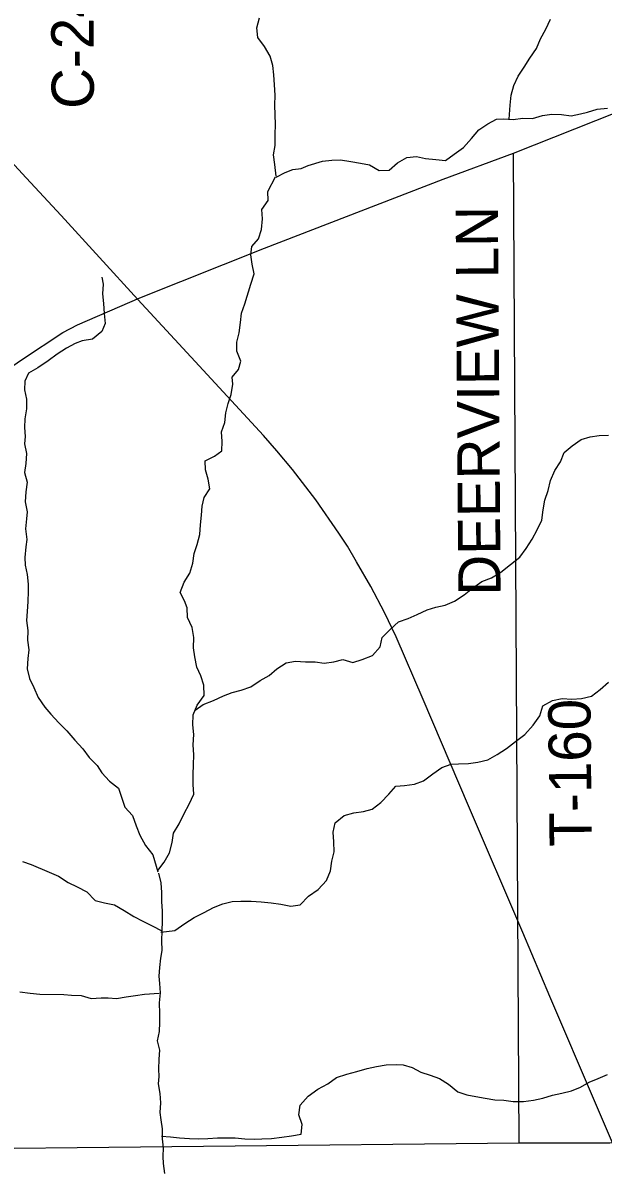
# Model space of a CAD drawing. Extents: x 1985906 to 2277390, y 930619 to 1324581.
# Drawn here: x 2127337 to 2131455, y 1129372 to 1137477 of the extents above; entities that cross this region are included whole.
import ezdxf

# ---------------------------------------------------------------- set-up
doc = ezdxf.new("R2010")
doc.units = 0
for name, color, linetype in [('GM_X_County_Road_Text', 7, 'Continuous'), ('GM_X_Minor_River', 7, 'Continuous'), ('GM_X_Rail_Line', 7, 'Continuous'), ('GM_X_State_Route', 7, 'Continuous'), ('GM_X_Township_Road', 7, 'Continuous'), ('GM_X_Township_Road_Text', 7, 'Continuous'), ('GM_X_US_Route', 7, 'Continuous')]:
    doc.layers.add(name, color=color, linetype=linetype)

msp = doc.modelspace()

# ---------------------------------------------------------------- linework, layer by layer
at = {"layer": 'GM_X_Minor_River'}
for points in [[(2129135.2, 1136388.4), (2129126.3, 1136471.2), (2129115.4, 1136539.6), (2129128.6, 1136607.6), (2129128, 1136685.8), (2129129.2, 1136756), (2129128.4, 1136824.2), (2129125.5, 1136892.5), (2129126.8, 1136964.7), (2129122, 1137037), (2129119.2, 1137107.3), (2129112.4, 1137175.6), (2129093.4, 1137240.2), (2129052.4, 1137309.1), (2129005.3, 1137374.2), (2128998.5, 1137442.5), (2129017.8, 1137512.4)], [(2130789.5, 1136794.9), (2130795, 1136892.5), (2130802.2, 1136964.6), (2130821.5, 1137032.4), (2130852.8, 1137098.1), (2130894.1, 1137163.5), (2130935.4, 1137227), (2130982.8, 1137294.3), (2131010.1, 1137364.1), (2131049.4, 1137431.6), (2131080.8, 1137503.2)], [(2129134.8, 1136382.7), (2129199.6, 1136415.7), (2129252.2, 1136436.8), (2129312.6, 1136443.7), (2129363.2, 1136464.9), (2129464.2, 1136495.2), (2129530.6, 1136504), (2129590.9, 1136504.9), (2129665, 1136493.5), (2129733.1, 1136482.3), (2129797.2, 1136469.1), (2129864.8, 1136429.8), (2129937.2, 1136432.4), (2129996.3, 1136483.5), (2130061.3, 1136522.5), (2130129.7, 1136529.3), (2130195.8, 1136514.1), (2130268, 1136506.7), (2130336.1, 1136499.5), (2130399.2, 1136544.5), (2130464.3, 1136593.5), (2130521.7, 1136656.6), (2130573, 1136717.9), (2130638, 1136760.9), (2130698.8, 1136793.9), (2130749.1, 1136795), (2130817.3, 1136791.7), (2130885.8, 1136800.5), (2130954.1, 1136799.3), (2131024.7, 1136820.1), (2131091.2, 1136828.9), (2131159.5, 1136827.7), (2131227.6, 1136816.4), (2131294.1, 1136831.3), (2131344.6, 1136842.4), (2131413.3, 1136865.2), (2131485.7, 1136872)], [(2128295.7, 1131463), (2128341.2, 1131521.8), (2128378.5, 1131587.3), (2128397.9, 1131661.2), (2128407.1, 1131727.2), (2128446.4, 1131794.7), (2128481.8, 1131866.3), (2128517.1, 1131933.9), (2128550.5, 1132003.5), (2128545.6, 1132071.8), (2128544.9, 1132144), (2128548.1, 1132212.2), (2128551.3, 1132284.3), (2128546.5, 1132354.7), (2128549.8, 1132426.8), (2128542.9, 1132495.2), (2128546.2, 1132567.3), (2128573.5, 1132635.1), (2128624.9, 1132704.3), (2128622.1, 1132776.6), (2128601.2, 1132843.2), (2128572.2, 1132905.9), (2128557.3, 1132978.4), (2128548.4, 1133042.8), (2128551.7, 1133115), (2128538.9, 1133187.4), (2128506, 1133258.2), (2128503.1, 1133326.5), (2128483.9, 1133377), (2128452.8, 1133435.8), (2128482.2, 1133507.4), (2128523.5, 1133572.9), (2128544.8, 1133642.7), (2128552, 1133712.8), (2128575.2, 1133776.6), (2128592.5, 1133846.5), (2128597.7, 1133914.6), (2128604.9, 1133982.7), (2128610, 1134046.8), (2128625.2, 1134108.8), (2128664.4, 1134170.2), (2128651.5, 1134238.7), (2128634.6, 1134305.2), (2128631.7, 1134369.5), (2128696.6, 1134402.4), (2128749.5, 1134439.6), (2128752.6, 1134507.7), (2128747.8, 1134574), (2128771, 1134641.8), (2128778.3, 1134709.9), (2128793.5, 1134775.8), (2128816.7, 1134839.6), (2128828, 1134913.6), (2128822.8, 1134963.9), (2128868, 1135017.2), (2128883.1, 1135077.2), (2128856.2, 1135147.9), (2128855.3, 1135212.1), (2128872.5, 1135278), (2128881.8, 1135350), (2128889, 1135418.1), (2128912.2, 1135483.9), (2128954.8, 1135623.6), (2128978.2, 1135697.4), (2128965.3, 1135765.8), (2128956.4, 1135830.2), (2128963.5, 1135890.3), (2129010.6, 1135945.6), (2129031.9, 1136011.4), (2129037.2, 1136085.6), (2129034.4, 1136153.8), (2129077.6, 1136217.2), (2129074.7, 1136279.5), (2129130.8, 1136384)], [(2127899, 1135672.8), (2127908.1, 1135622.4), (2127902.9, 1135554.3), (2127909.8, 1135486), (2127914.6, 1135415.7), (2127921.4, 1135343.3), (2127898.3, 1135287.6), (2127831.1, 1135232.6), (2127758.6, 1135221.9), (2127708, 1135202.7), (2127647.2, 1135169.7), (2127582.1, 1135126.8), (2127517, 1135079.8), (2127443.8, 1135028.9), (2127376.9, 1134992), (2127351.8, 1134934.3), (2127348.7, 1134872.2), (2127363.6, 1134807.7), (2127364.4, 1134737.4), (2127351.2, 1134667.5), (2127348.1, 1134605.3), (2127353, 1134541), (2127348.1, 1134491), (2127362.9, 1134420.5), (2127357.7, 1134350.3), (2127348.6, 1134286.3), (2127367.5, 1134217.8), (2127358.2, 1134149.7), (2127355, 1134079.5), (2127367.8, 1134007.1), (2127362.9, 1133957), (2127355.7, 1133886.9), (2127366.4, 1133810.5), (2127357.5, 1133758.5), (2127352.2, 1133684.4), (2127353.2, 1133628.2), (2127368.1, 1133561.7), (2127375, 1133493.3), (2127376.1, 1133443.2), (2127372.8, 1133371), (2127367.6, 1133300.9), (2127362.5, 1133236.8), (2127373.3, 1133166.3), (2127370.1, 1133096.2), (2127378.9, 1133027.8), (2127373.9, 1132965.7), (2127368.6, 1132893.6), (2127383.5, 1132825.1), (2127414.5, 1132760.3), (2127445.4, 1132689.6), (2127492.5, 1132622.5), (2127535.8, 1132571.6), (2127593, 1132510.3), (2127650.2, 1132453.1), (2127705.3, 1132387.9), (2127762.5, 1132326.7), (2127807.7, 1132263.7), (2127864.9, 1132206.5), (2127898.2, 1132155.7), (2127951.4, 1132096.6), (2128016.8, 1132047.2), (2128039.7, 1131974.6), (2128060.7, 1131912), (2128115.9, 1131852.8), (2128140.8, 1131780.2), (2128167.7, 1131713.5), (2128206.7, 1131640.6), (2128259.7, 1131573.4), (2128295.7, 1131454.1)], [(2128560.8, 1132599.2), (2128617.8, 1132640.3), (2128690.6, 1132669.1), (2128761.5, 1132701.9), (2128822.1, 1132724.9), (2128886.7, 1132741.8), (2128955.4, 1132764.6), (2129020.5, 1132809.6), (2129085.4, 1132846.5), (2129140.5, 1132893.7), (2129205.5, 1132936.6), (2129272, 1132947.5), (2129344.3, 1132944.1), (2129412.5, 1132942.9), (2129476.7, 1132933.7), (2129543.1, 1132942.6), (2129607.7, 1132959.4), (2129679.6, 1132938.1), (2129746.3, 1132959), (2129819.1, 1132987.7), (2129872.4, 1133049), (2129887.6, 1133114.9), (2129942.9, 1133172.1), (2130004.1, 1133227.2), (2130070.8, 1133250), (2130135.6, 1133278.9), (2130206.4, 1133311.8), (2130269.1, 1133330.7), (2130333.6, 1133345.6), (2130400.4, 1133374.5), (2130469.4, 1133417.4), (2130528.6, 1133466.5), (2130593.7, 1133513.4), (2130662.4, 1133540.3), (2130729.4, 1133579.2), (2130796.7, 1133634.2), (2130863.8, 1133685.1), (2130909.1, 1133746.5), (2130952.5, 1133813.9), (2130987.7, 1133879.5), (2131021.1, 1133949.1), (2131030.4, 1134021.2), (2131041.6, 1134089.2), (2131064.9, 1134159), (2131082.2, 1134228.9), (2131113.6, 1134300.6), (2131152.8, 1134362.1), (2131178.1, 1134427.8), (2131235.2, 1134476.9), (2131300.2, 1134521.9), (2131362.8, 1134540.8), (2131427.3, 1134549.7), (2131493.6, 1134552.5)], [(2128317.7, 1131025.1), (2128415.2, 1131036.9), (2128486.3, 1131085.8), (2128553.4, 1131128.7), (2128624.3, 1131163.5), (2128689.2, 1131200.5), (2128755.9, 1131225.3), (2128822.5, 1131242.2), (2128884.8, 1131245.1), (2128957.1, 1131243.8), (2129027.4, 1131240.5), (2129099.6, 1131233.2), (2129167.7, 1131223.9), (2129239.8, 1131210.6), (2129306.3, 1131219.4), (2129365.6, 1131280.5), (2129432.7, 1131327.5), (2129492.1, 1131392.6), (2129519.4, 1131460.3), (2129530.6, 1131528.3), (2129545.8, 1131594.3), (2129545.1, 1131666.5), (2129540.2, 1131734.8), (2129553.4, 1131800.8), (2129616.6, 1131851.8), (2129685.2, 1131870.6), (2129753.7, 1131881.4), (2129816.3, 1131898.4), (2129877.4, 1131945.4), (2129934.6, 1132004.6), (2129983.8, 1132059.8), (2130046.2, 1132066.8), (2130116.7, 1132075.5), (2130181.4, 1132098.4), (2130246.5, 1132147.4), (2130309.6, 1132194.4), (2130376.3, 1132217.3), (2130428.6, 1132220.3), (2130500.9, 1132221), (2130565.4, 1132231.9), (2130638, 1132248.7), (2130702.9, 1132285.6), (2130770, 1132328.5), (2130833.1, 1132377.6), (2130900.3, 1132428.5), (2130957.7, 1132493.7), (2131007, 1132561), (2131028.3, 1132630.8), (2131095.3, 1132669.8), (2131163.8, 1132682.6), (2131232.1, 1132677.3), (2131302.4, 1132682.1), (2131373, 1132698.8), (2131434.2, 1132747.9), (2131493.3, 1132799)], [(2127334.8, 1131525.9), (2127396.7, 1131504.7), (2127524.3, 1131450.2), (2127590.2, 1131423), (2127659.7, 1131377.6), (2127723.4, 1131346.3), (2127791.1, 1131311), (2127850.3, 1131249.7), (2127916.3, 1131232.5), (2127988.4, 1131219.2), (2128056, 1131179.8), (2128125.6, 1131136.4), (2128189.3, 1131103.2), (2128255, 1131069.9), (2128322.7, 1131034.6)], [(2128299.7, 1131444.2), (2128316.6, 1131375.7), (2128321.4, 1131307.4), (2128322.3, 1131243.2), (2128325.1, 1131174.9), (2128325.9, 1131102.7), (2128324.7, 1131034.5), (2128321.5, 1130962.3), (2128324.3, 1130894.1), (2128315.3, 1130840.1), (2128306.1, 1130774), (2128303, 1130711.9), (2128308.2, 1130661.6), (2128311, 1130593.4), (2128303.8, 1130523.3), (2128306.5, 1130449), (2128307.4, 1130382.8), (2128304.3, 1130320.7), (2128291.1, 1130254.7), (2128306, 1130188.2), (2128302.9, 1130124.1), (2128299.6, 1130051.9), (2128302.7, 1129999.7), (2128297.8, 1129947.6), (2128308.7, 1129881.2), (2128313.5, 1129812.9), (2128310.4, 1129744.8), (2128317.5, 1129692.4), (2128326.5, 1129630.1), (2128327.2, 1129557.9), (2128332.1, 1129493.6), (2128331.1, 1129433.4), (2128334.2, 1129383.2), (2128343, 1129312.8)], [(2127316.7, 1130601.3), (2127388.9, 1130592), (2127459.1, 1130584.7), (2127627.8, 1130581.7), (2127682, 1130578.7), (2127750.2, 1130575.4), (2127822.2, 1130554.1), (2127892.6, 1130558.8), (2127942.8, 1130557.9), (2128001, 1130554.8), (2128071.5, 1130565.6), (2128135.9, 1130574.5), (2128200.4, 1130585.3), (2128304.3, 1130591.6)], [(2128321.5, 1129578), (2128385.7, 1129572.8), (2128447.9, 1129565.7), (2128520.1, 1129560.4), (2128580.4, 1129559.3), (2128650.7, 1129560), (2128719.1, 1129564.8), (2128771.3, 1129565.9), (2128843.6, 1129564.6), (2128911.8, 1129559.3), (2128982.1, 1129556.1), (2129034.4, 1129559.1), (2129102.7, 1129561.9), (2129175.2, 1129570.6), (2129243.7, 1129579.4), (2129312.2, 1129592.2), (2129319.4, 1129660.3), (2129296.5, 1129728.9), (2129305.7, 1129797), (2129361.1, 1129862.2), (2129430.2, 1129911.1), (2129501.2, 1129949.9), (2129564.2, 1129992.9), (2129637, 1130017.7), (2129707.6, 1130036.5), (2129780.3, 1130057.2), (2129846.8, 1130072.1), (2129915.3, 1130082.9), (2129985.7, 1130085.6), (2130035.9, 1130082.7), (2130099.9, 1130065.5), (2130161.6, 1130032.3), (2130227.5, 1130011), (2130293.3, 1129985.8), (2130359, 1129946.5), (2130424.3, 1129893.1), (2130488.2, 1129869.9), (2130552.3, 1129858.7), (2130618.4, 1129847.5), (2130686.5, 1129836.2), (2130750.7, 1129833.1), (2130816.9, 1129823.8), (2130889.2, 1129824.5), (2130961.7, 1129833.3), (2131026.2, 1129846.1), (2131096.9, 1129868.9), (2131161.4, 1129881.8), (2131230, 1129898.6), (2131294.8, 1129925.6), (2131355.6, 1129960.6), (2131420.4, 1129985.5), (2131487.2, 1130014.4)]]:
    msp.add_lwpolyline(points, dxfattribs=at)
at = {"layer": 'GM_X_Rail_Line'}
msp.add_lwpolyline([(2133572.7, 1124731.6), (2133429.5, 1125064.5), (2132764.9, 1126619.2), (2131928.4, 1128579.1), (2131402, 1129810.9), (2131077.9, 1130568.8), (2130884.3, 1131022.3), (2130499.6, 1131921.3), (2130177.2, 1132675.6), (2129985.4, 1133121.6), (2129904.4, 1133293), (2129807, 1133477.2), (2129706.1, 1133652.1), (2129640.3, 1133763.4), (2129579.6, 1133856.1), (2129416.4, 1134092.8), (2129250.3, 1134308.5), (2129140.1, 1134440.8), (2129044.5, 1134548.7), (2128588, 1135044.2), (2128154.3, 1135515.2), (2127609.2, 1136109.3), (2127360.9, 1136377.4), (2127087.5, 1136674.2)], dxfattribs=at)
at = {"layer": 'GM_X_State_Route'}
msp.add_lwpolyline([(2124187.8, 1129468.8), (2125742.8, 1129479.4), (2126378.1, 1129482.1), (2130859.2, 1129530.4), (2131503.7, 1129530.4), (2132983.4, 1129551.4), (2134376.8, 1129565.6)], dxfattribs=at)
at = {"layer": 'GM_X_Township_Road'}
msp.add_lwpolyline([(2130859.2, 1129530.4), (2130818.4, 1136553.3)], dxfattribs=at)
at = {"layer": 'GM_X_US_Route'}
msp.add_lwpolyline([(2124728.5, 1132501.1), (2124847.5, 1133131.3), (2124877.1, 1133262.7), (2124949.3, 1133392.3), (2124999.2, 1133483), (2125082.5, 1133592.2), (2125147.3, 1133662.5), (2125232.4, 1133754.3), (2125270, 1133784.9), (2125543.2, 1133947.9), (2126424.1, 1134473.5), (2126930.9, 1134814.6), (2127334.4, 1135090.2), (2127621.9, 1135280.7), (2127724.1, 1135333.3), (2128167.2, 1135525.6), (2129051.6, 1135878.2), (2130319, 1136368.7), (2130818.4, 1136553.3), (2131689, 1136897.1)], dxfattribs=at)

# ---------------------------------------------------------------- texts
at = {"layer": 'GM_X_County_Road_Text'}
msp.add_text('C-24', height=300, rotation=90.3429, dxfattribs=at).set_placement((2127842.5, 1136867.6))
at = {"layer": 'GM_X_Township_Road_Text'}
for s, rotation, p in [('DEERVIEW LN', 90.40437, (2130727.8, 1133414.1)), ('T-160', 90.5614, (2131375.2, 1131633.6))]:
    msp.add_text(s, height=300, rotation=rotation, dxfattribs=at).set_placement(p)

doc.saveas('drawing.dxf')
